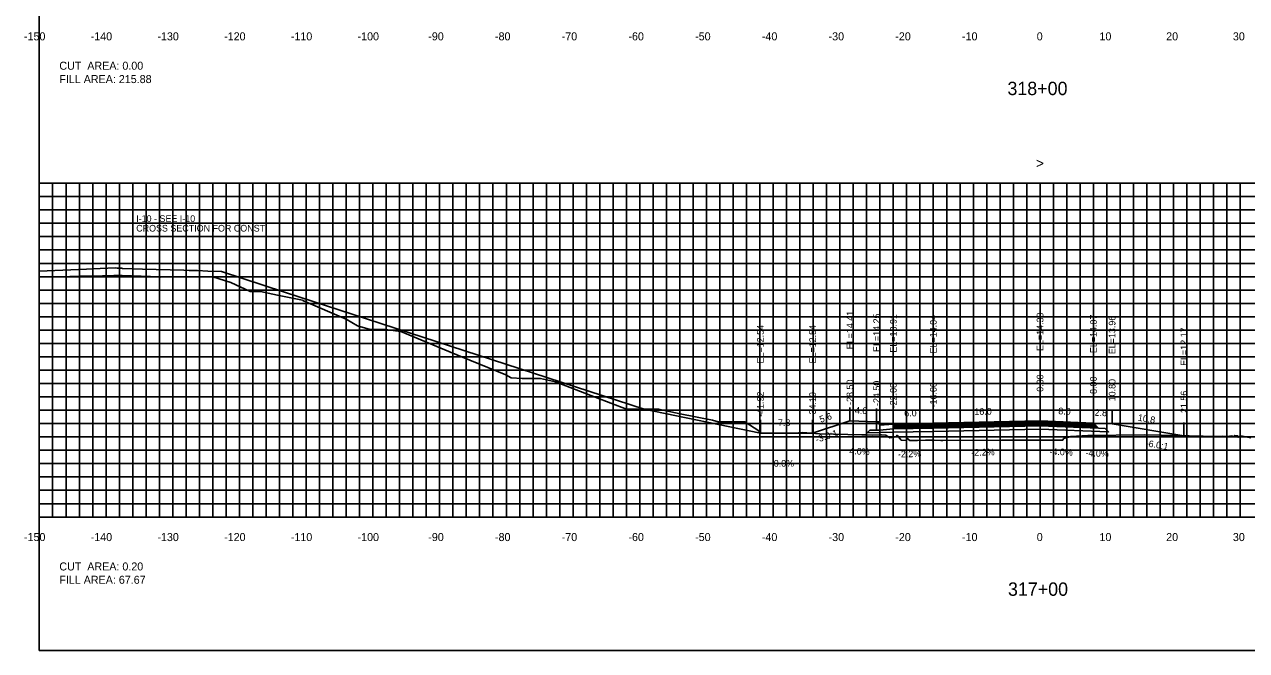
# Model space of a CAD drawing. Extents: x 1797652 to 1804145, y 245981 to 250269.
# Drawn here: x 1802478.8 to 1802661.9, y 250079.4 to 250173.2 of the extents above; entities that cross this region are included whole.
import ezdxf

# ---------------------------------------------------------------- set-up
doc = ezdxf.new("R2010")
doc.units = 0
for name, color, linetype in [('1', 7, 'Continuous'), ('10', 7, 'Continuous'), ('3', 7, 'Continuous'), ('4', 7, 'Continuous'), ('60', 7, 'Continuous'), ('ANNO-TXT', 7, 'Continuous'), ('BASE', 7, 'Continuous'), ('CL-CNST', 7, 'Continuous'), ('Level 62', 7, 'Continuous'), ('LOWER BINDER', 7, 'Continuous'), ('M-ROADS', 7, 'Continuous'), ('UPPER BINDER', 7, 'Continuous'), ('WEARING', 7, 'Continuous')]:
    doc.layers.add(name, color=color, linetype=linetype)

msp = doc.modelspace()

# ---------------------------------------------------------------- linework, layer by layer
for p, q in [((1802602.5, 250113.84), (1802602.5, 250115.84)), ((1802631, 250113.82), (1802631, 250115.82)), ((1802589.08, 250111.97), (1802589.08, 250113.97)), ((1802596.9, 250111.97), (1802596.9, 250113.97)), ((1802606.5, 250113.68), (1802606.5, 250115.68)), ((1802609, 250113.34), (1802609, 250115.34)), ((1802615, 250113.47), (1802615, 250115.47)), ((1802639, 250113.5), (1802639, 250115.5)), ((1802641.8, 250113.39), (1802641.8, 250115.39)), ((1802652.56, 250111.6), (1802652.56, 250113.6))]:
    msp.add_line(p, q)
for points in [[(1802481, 250079.43), (1802781, 250079.43), (1802781, 250269.43), (1802481, 250269.43)], [(1802609, 250113.34), (1802607, 250113.18), (1802606.83, 250113.68), (1802606.5, 250113.68), (1802606.5, 250112.46), (1802607, 250112.46), (1802609, 250112.62)]]:
    msp.add_lwpolyline(points, close=True)
at = {"layer": '60'}
for p, q in [((1802480.94, 250149.43), (1802481, 250149.43)), ((1802481, 250099.43), (1802481, 250149.43)), ((1802480.94, 250139.43), (1802481, 250139.43)), ((1802480.94, 250129.43), (1802481, 250129.43)), ((1802480.94, 250119.43), (1802481, 250119.43)), ((1802480.94, 250109.43), (1802481, 250109.43)), ((1802480.94, 250099.43), (1802481, 250099.43)), ((1802481, 250099.43), (1802781, 250099.43)), ((1802481, 250099.37), (1802481, 250099.43)), ((1802491, 250099.37), (1802491, 250099.43)), ((1802501, 250099.37), (1802501, 250099.43)), ((1802511, 250099.37), (1802511, 250099.43)), ((1802521, 250099.37), (1802521, 250099.43)), ((1802531, 250099.37), (1802531, 250099.43)), ((1802541, 250099.37), (1802541, 250099.43)), ((1802551, 250099.37), (1802551, 250099.43)), ((1802561, 250099.37), (1802561, 250099.43)), ((1802571, 250099.37), (1802571, 250099.43)), ((1802581, 250099.37), (1802581, 250099.43)), ((1802591, 250099.37), (1802591, 250099.43)), ((1802601, 250099.37), (1802601, 250099.43)), ((1802611, 250099.37), (1802611, 250099.43)), ((1802621, 250099.37), (1802621, 250099.43)), ((1802631, 250099.37), (1802631, 250099.43)), ((1802641, 250099.37), (1802641, 250099.43)), ((1802651, 250099.37), (1802651, 250099.43)), ((1802661, 250099.37), (1802661, 250099.43))]:
    msp.add_line(p, q, dxfattribs=at)
at = {"layer": 'BASE'}
msp.add_lwpolyline([(1802609, 250112.62), (1802615, 250112.75), (1802631, 250113.1), (1802639.75, 250112.75), (1802640.75, 250112.71), (1802641.27, 250112.19), (1802631, 250112.6), (1802615, 250112.25), (1802609, 250112.12), (1802605.09, 250112.03), (1802605.5, 250112.44), (1802606.5, 250112.46), (1802607, 250112.46)], close=True, dxfattribs=at)
at = {"layer": 'CL-CNST'}
msp.add_line((1802571.64, 250115.58), (1802589.08, 250111.97), dxfattribs=at)
for points in [[(1802481, 250136.24), (1802488.09, 250136.55), (1802489.04, 250136.59), (1802492.37, 250136.74), (1802492.67, 250136.73), (1802493.4, 250136.7), (1802493.41, 250136.68), (1802493.45, 250136.64), (1802496.48, 250136.57), (1802502.64, 250136.42), (1802503.47, 250136.38), (1802504.7, 250136.34), (1802506.24, 250136.27), (1802508.3, 250136.19), (1802517.77, 250133.11), (1802571.64, 250115.58)], [(1802589.08, 250111.97), (1802596.9, 250111.97), (1802602.5, 250113.84), (1802606.5, 250113.68), (1802606.83, 250113.68), (1802607, 250113.18), (1802609, 250113.34), (1802615, 250113.47), (1802631, 250113.82), (1802639, 250113.5), (1802641.8, 250113.39), (1802652.56, 250111.6)]]:
    msp.add_lwpolyline(points, dxfattribs=at)
at = {"layer": 'Level 62'}
for p, q in [((1802481, 250149.43), (1802781, 250149.43)), ((1802481, 250099.43), (1802481, 250149.43)), ((1802483, 250099.43), (1802483, 250149.43)), ((1802485, 250099.43), (1802485, 250149.43)), ((1802487, 250099.43), (1802487, 250149.43)), ((1802489, 250099.43), (1802489, 250149.43)), ((1802491, 250099.43), (1802491, 250149.43)), ((1802493, 250099.43), (1802493, 250149.43)), ((1802495, 250099.43), (1802495, 250149.43)), ((1802497, 250099.43), (1802497, 250149.43)), ((1802499, 250099.43), (1802499, 250149.43)), ((1802501, 250099.43), (1802501, 250149.43)), ((1802503, 250099.43), (1802503, 250149.43)), ((1802505, 250099.43), (1802505, 250149.43)), ((1802507, 250099.43), (1802507, 250149.43)), ((1802509, 250099.43), (1802509, 250149.43)), ((1802511, 250099.43), (1802511, 250149.43)), ((1802513, 250099.43), (1802513, 250149.43)), ((1802515, 250099.43), (1802515, 250149.43)), ((1802517, 250099.43), (1802517, 250149.43)), ((1802519, 250099.43), (1802519, 250149.43)), ((1802521, 250099.43), (1802521, 250149.43)), ((1802523, 250099.43), (1802523, 250149.43)), ((1802525, 250099.43), (1802525, 250149.43)), ((1802527, 250099.43), (1802527, 250149.43)), ((1802529, 250099.43), (1802529, 250149.43)), ((1802531, 250099.43), (1802531, 250149.43)), ((1802533, 250099.43), (1802533, 250149.43)), ((1802535, 250099.43), (1802535, 250149.43)), ((1802537, 250099.43), (1802537, 250149.43)), ((1802539, 250099.43), (1802539, 250149.43)), ((1802541, 250099.43), (1802541, 250149.43)), ((1802543, 250099.43), (1802543, 250149.43)), ((1802545, 250099.43), (1802545, 250149.43)), ((1802547, 250099.43), (1802547, 250149.43)), ((1802549, 250099.43), (1802549, 250149.43)), ((1802551, 250099.43), (1802551, 250149.43)), ((1802553, 250099.43), (1802553, 250149.43)), ((1802555, 250099.43), (1802555, 250149.43)), ((1802557, 250099.43), (1802557, 250149.43)), ((1802559, 250099.43), (1802559, 250149.43)), ((1802561, 250099.43), (1802561, 250149.43)), ((1802563, 250099.43), (1802563, 250149.43)), ((1802565, 250099.43), (1802565, 250149.43)), ((1802567, 250099.43), (1802567, 250149.43)), ((1802569, 250099.43), (1802569, 250149.43)), ((1802571, 250099.43), (1802571, 250149.43)), ((1802573, 250099.43), (1802573, 250149.43)), ((1802575, 250099.43), (1802575, 250149.43)), ((1802577, 250099.43), (1802577, 250149.43)), ((1802579, 250099.43), (1802579, 250149.43)), ((1802581, 250099.43), (1802581, 250149.43)), ((1802583, 250099.43), (1802583, 250149.43)), ((1802585, 250099.43), (1802585, 250149.43)), ((1802587, 250099.43), (1802587, 250149.43)), ((1802589, 250099.43), (1802589, 250149.43)), ((1802591, 250099.43), (1802591, 250149.43)), ((1802593, 250099.43), (1802593, 250149.43)), ((1802595, 250099.43), (1802595, 250149.43)), ((1802597, 250099.43), (1802597, 250149.43)), ((1802599, 250099.43), (1802599, 250149.43)), ((1802601, 250099.43), (1802601, 250149.43)), ((1802603, 250099.43), (1802603, 250149.43)), ((1802605, 250099.43), (1802605, 250149.43)), ((1802607, 250099.43), (1802607, 250149.43)), ((1802609, 250099.43), (1802609, 250149.43)), ((1802611, 250099.43), (1802611, 250149.43)), ((1802613, 250099.43), (1802613, 250149.43)), ((1802615, 250099.43), (1802615, 250149.43)), ((1802617, 250099.43), (1802617, 250149.43)), ((1802619, 250099.43), (1802619, 250149.43)), ((1802621, 250099.43), (1802621, 250149.43)), ((1802623, 250099.43), (1802623, 250149.43)), ((1802625, 250099.43), (1802625, 250149.43)), ((1802627, 250099.43), (1802627, 250149.43)), ((1802629, 250099.43), (1802629, 250149.43)), ((1802631, 250099.43), (1802631, 250149.43)), ((1802633, 250099.43), (1802633, 250149.43)), ((1802635, 250099.43), (1802635, 250149.43)), ((1802637, 250099.43), (1802637, 250149.43)), ((1802639, 250099.43), (1802639, 250149.43)), ((1802641, 250099.43), (1802641, 250149.43)), ((1802643, 250099.43), (1802643, 250149.43)), ((1802645, 250099.43), (1802645, 250149.43)), ((1802647, 250099.43), (1802647, 250149.43)), ((1802649, 250099.43), (1802649, 250149.43)), ((1802651, 250099.43), (1802651, 250149.43)), ((1802653, 250099.43), (1802653, 250149.43)), ((1802655, 250099.43), (1802655, 250149.43)), ((1802657, 250099.43), (1802657, 250149.43)), ((1802659, 250099.43), (1802659, 250149.43)), ((1802661, 250099.43), (1802661, 250149.43)), ((1802481, 250147.43), (1802781, 250147.43)), ((1802481, 250145.43), (1802781, 250145.43)), ((1802481, 250143.43), (1802781, 250143.43)), ((1802481, 250141.43), (1802781, 250141.43)), ((1802481, 250139.43), (1802781, 250139.43)), ((1802481, 250137.43), (1802781, 250137.43)), ((1802481, 250135.43), (1802781, 250135.43)), ((1802481, 250133.43), (1802781, 250133.43)), ((1802481, 250131.43), (1802781, 250131.43)), ((1802481, 250129.43), (1802781, 250129.43)), ((1802481, 250127.43), (1802781, 250127.43)), ((1802481, 250125.43), (1802781, 250125.43)), ((1802481, 250123.43), (1802781, 250123.43)), ((1802481, 250121.43), (1802781, 250121.43)), ((1802481, 250119.43), (1802781, 250119.43)), ((1802481, 250117.43), (1802781, 250117.43)), ((1802481, 250115.43), (1802781, 250115.43)), ((1802481, 250113.43), (1802781, 250113.43)), ((1802481, 250111.43), (1802781, 250111.43)), ((1802481, 250109.43), (1802781, 250109.43)), ((1802481, 250107.43), (1802781, 250107.43)), ((1802481, 250105.43), (1802781, 250105.43)), ((1802481, 250103.43), (1802781, 250103.43)), ((1802481, 250101.43), (1802781, 250101.43)), ((1802481, 250099.43), (1802781, 250099.43))]:
    msp.add_line(p, q, dxfattribs=at)
at = {"layer": 'LOWER BINDER'}
for points in [[(1802615, 250113.13), (1802631, 250113.48), (1802639.36, 250113.15), (1802639.55, 250112.95), (1802631, 250113.29), (1802615, 250112.94), (1802609, 250112.81), (1802609, 250113)], [(1802615, 250112.94), (1802631, 250113.29), (1802639.55, 250112.95), (1802639.75, 250112.75), (1802631, 250113.1), (1802615, 250112.75), (1802609, 250112.62), (1802609, 250112.81)]]:
    msp.add_lwpolyline(points, close=True, dxfattribs=at)
at = {"layer": 'M-ROADS'}
msp.add_lwpolyline([(1802481, 250135.37), (1802483.82, 250135.42), (1802485.59, 250135.45), (1802486.96, 250135.49), (1802490.47, 250135.58), (1802492.16, 250135.61), (1802492.84, 250135.61), (1802493.44, 250135.61), (1802497.65, 250135.44), (1802499.16, 250135.38), (1802501.69, 250135.39), (1802502.14, 250135.39), (1802503.1, 250135.39), (1802504.99, 250135.39), (1802507.01, 250135.39), (1802509.72, 250134.56), (1802512.62, 250133.2), (1802513.37, 250133.2), (1802514.17, 250133.2), (1802516.72, 250132.67), (1802520.43, 250131.9), (1802520.49, 250131.88), (1802520.62, 250131.82), (1802526.97, 250129.08), (1802528.67, 250128.07), (1802530.57, 250127.52), (1802531.68, 250127.52), (1802532.85, 250127.52), (1802535.21, 250127.22), (1802544.18, 250123.46), (1802550.92, 250120.72), (1802551.72, 250120.3), (1802553.36, 250120.17), (1802554.79, 250120.17), (1802556.13, 250120.17), (1802558.38, 250119.66), (1802564.29, 250117.39), (1802569.02, 250115.59), (1802569.59, 250115.58), (1802571.34, 250115.58), (1802573.2, 250115.58), (1802573.83, 250115.59), (1802577.07, 250114.91), (1802581.9, 250113.95), (1802582.74, 250113.67), (1802584.19, 250113.67), (1802585.51, 250113.67), (1802586.76, 250113.67), (1802588.85, 250112.36), (1802589.08, 250111.99), (1802589.53, 250111.99), (1802591.59, 250111.98), (1802591.95, 250111.98), (1802594.09, 250111.97), (1802595.44, 250112.08), (1802597.92, 250111.9), (1802604.3, 250111.73), (1802605.09, 250111.74), (1802605.87, 250111.69), (1802607.01, 250111.74), (1802607.21, 250111.73), (1802607.89, 250111.67), (1802608.48, 250111.28), (1802609.41, 250111.44), (1802609.56, 250111.69), (1802609.99, 250111.18), (1802610.2, 250110.92), (1802610.91, 250110.89), (1802611.03, 250111.22), (1802611.49, 250110.88), (1802612.56, 250110.9), (1802612.61, 250110.9), (1802613.81, 250110.92), (1802613.86, 250110.92), (1802613.92, 250110.92), (1802614.77, 250110.93), (1802614.89, 250110.9), (1802615.19, 250110.93), (1802616.14, 250110.9), (1802616.44, 250110.9), (1802625.23, 250110.93), (1802627.96, 250110.94), (1802628.12, 250110.94), (1802628.22, 250110.94), (1802629.37, 250110.93), (1802629.52, 250110.94), (1802629.79, 250110.93), (1802630.65, 250110.93), (1802631.39, 250110.92), (1802631.9, 250110.93), (1802632.56, 250110.93), (1802633.12, 250110.95), (1802633.32, 250110.94), (1802634.37, 250110.94), (1802634.58, 250111.2), (1802635.63, 250111.5), (1802638.16, 250111.64), (1802646.62, 250111.74), (1802649.16, 250111.68), (1802655.42, 250111.53), (1802656.98, 250111.5), (1802658.3, 250111.53), (1802658.52, 250111.51), (1802658.68, 250111.5), (1802658.99, 250111.48), (1802659.74, 250111.57), (1802660.13, 250111.48), (1802660.19, 250111.65), (1802660.6, 250111.57), (1802660.68, 250111.52), (1802660.68, 250111.35), (1802660.95, 250111.57), (1802661.09, 250111.57), (1802662.58, 250111.28)], dxfattribs=at)
at = {"layer": 'UPPER BINDER'}
msp.add_lwpolyline([(1802639.36, 250113.15), (1802639.16, 250113.35), (1802631, 250113.67), (1802615, 250113.32), (1802609, 250113.19), (1802609, 250113), (1802615, 250113.13), (1802631, 250113.48)], close=True, dxfattribs=at)
at = {"layer": 'WEARING'}
msp.add_lwpolyline([(1802639.16, 250113.35), (1802639, 250113.5), (1802631, 250113.82), (1802615, 250113.47), (1802609, 250113.34), (1802609, 250113.19), (1802615, 250113.32), (1802631, 250113.67)], close=True, dxfattribs=at)

# ---------------------------------------------------------------- texts
for s, rotation, p in [('-3.0:1', 18.4349, (1802597.53, 250110.53)), ('-6.0:1', 350.5377, (1802646.77, 250110.03))]:
    msp.add_text(s, height=1, rotation=rotation).set_placement(p)
at = {"layer": '1'}
for s, p in [('318+00', (1802626.11, 250162.63)), ('317+00', (1802626.19, 250087.63))]:
    msp.add_text(s, height=2, dxfattribs=at).set_placement(p)
at = {"layer": '10'}
for s, p in [('-150', (1802478.7, 250170.83)), ('-140', (1802488.7, 250170.83)), ('-130', (1802498.7, 250170.83)), ('-120', (1802508.7, 250170.83)), ('-110', (1802518.7, 250170.83)), ('-100', (1802528.7, 250170.83)), ('-90', (1802539.3, 250170.83)), ('-80', (1802549.3, 250170.83)), ('-70', (1802559.3, 250170.83)), ('-60', (1802569.3, 250170.83)), ('-50', (1802579.3, 250170.83)), ('-40', (1802589.3, 250170.83)), ('-30', (1802599.3, 250170.83)), ('-20', (1802609.3, 250170.83)), ('-10', (1802619.3, 250170.83)), ('0', (1802630.5, 250170.83)), ('10', (1802639.9, 250170.83)), ('20', (1802649.9, 250170.83)), ('30', (1802659.9, 250170.83)), ('-150', (1802478.7, 250095.83)), ('-140', (1802488.7, 250095.83)), ('-130', (1802498.7, 250095.83)), ('-120', (1802508.7, 250095.83)), ('-110', (1802518.7, 250095.83)), ('-100', (1802528.7, 250095.83)), ('-90', (1802539.3, 250095.83)), ('-80', (1802549.3, 250095.83)), ('-70', (1802559.3, 250095.83)), ('-60', (1802569.3, 250095.83)), ('-50', (1802579.3, 250095.83)), ('-40', (1802589.3, 250095.83)), ('-30', (1802599.3, 250095.83)), ('-20', (1802609.3, 250095.83)), ('-10', (1802619.3, 250095.83)), ('0', (1802630.5, 250095.83)), ('10', (1802639.9, 250095.83)), ('20', (1802649.9, 250095.83)), ('30', (1802659.9, 250095.83))]:
    msp.add_text(s, height=1.2, dxfattribs=at).set_placement(p)
at = {"layer": '3'}
for s, p in [('I-10 - SEE I-10', (1802495.52, 250143.63)), ('CROSS SECTION FOR CONST ', (1802495.52, 250142.19))]:
    msp.add_text(s, height=1, dxfattribs=at).set_placement(p)
for s, p in [('EL=14.41', (1802603, 250124.56)), ('EL=14.25', (1802607, 250124.15)), ('EL=13.91', (1802609.5, 250124.06)), ('EL=14.04', (1802615.5, 250123.94)), ('EL=14.39', (1802631.5, 250124.3)), ('EL=14.07', (1802639.5, 250123.98)), ('EL=13.96', (1802642.3, 250123.82)), ('EL=12.54', (1802589.58, 250122.44)), ('EL=12.54', (1802597.4, 250122.44)), ('EL=12.17', (1802653.06, 250122.07)), ('-28.50', (1802603, 250116.22)), ('-24.50', (1802607, 250116.06)), ('-22.00', (1802609.5, 250115.72)), ('-16.00', (1802615.5, 250115.85)), ('0.00', (1802631.5, 250118.19)), ('8.00', (1802639.5, 250117.87)), ('10.80', (1802642.3, 250116.76)), ('-41.92', (1802589.58, 250114.43)), ('-34.10', (1802597.4, 250114.35)), ('21.56', (1802653.06, 250115))]:
    msp.add_text(s, height=1, rotation=90, dxfattribs=at).set_placement(p)
at = {"layer": '4'}
for s, rotation, p in [('4.0', 357.7094, (1802603.23, 250114.91)), ('8.0', 357.7094, (1802633.72, 250114.82)), ('5.6', 18.4349, (1802598.12, 250113.54)), ('6.0', 1.2603, (1802610.65, 250114.48)), ('16.0', 1.2603, (1802621.16, 250114.71)), ('2.8', 357.7094, (1802639.16, 250114.6)), ('10.8', 350.5377, (1802645.6, 250113.87)), ('4.0%', 357.7094, (1802602.39, 250108.84)), ('-2.2%', 1.2603, (1802609.7, 250108.35)), ('-2.2%', 1.2603, (1802620.7, 250108.6)), ('-4.0%', 357.7094, (1802632.39, 250108.76)), ('-4.0%', 357.7094, (1802637.79, 250108.55))]:
    msp.add_text(s, height=1, rotation=rotation, dxfattribs=at).set_placement(p)
for s, p in [('7.8', (1802591.71, 250113.07)), ('0.0%', (1802591.08, 250106.97))]:
    msp.add_text(s, height=1, dxfattribs=at).set_placement(p)
at = {"layer": '60'}
for s, height, p in [('>', 1.5, (1802630.39, 250151.68)), ('-', 0.0001, (1802481, 250099.43))]:
    msp.add_text(s, height=height, dxfattribs=at).set_placement(p)
at = {"layer": 'ANNO-TXT'}
for s, p in [('CUT  AREA: 0.00', (1802484, 250166.43)), ('FILL AREA: 215.88', (1802484, 250164.43)), ('CUT  AREA: 0.20', (1802484, 250091.43)), ('FILL AREA: 67.67', (1802484, 250089.43))]:
    msp.add_text(s, height=1.2, dxfattribs=at).set_placement(p)

doc.saveas('drawing.dxf')
